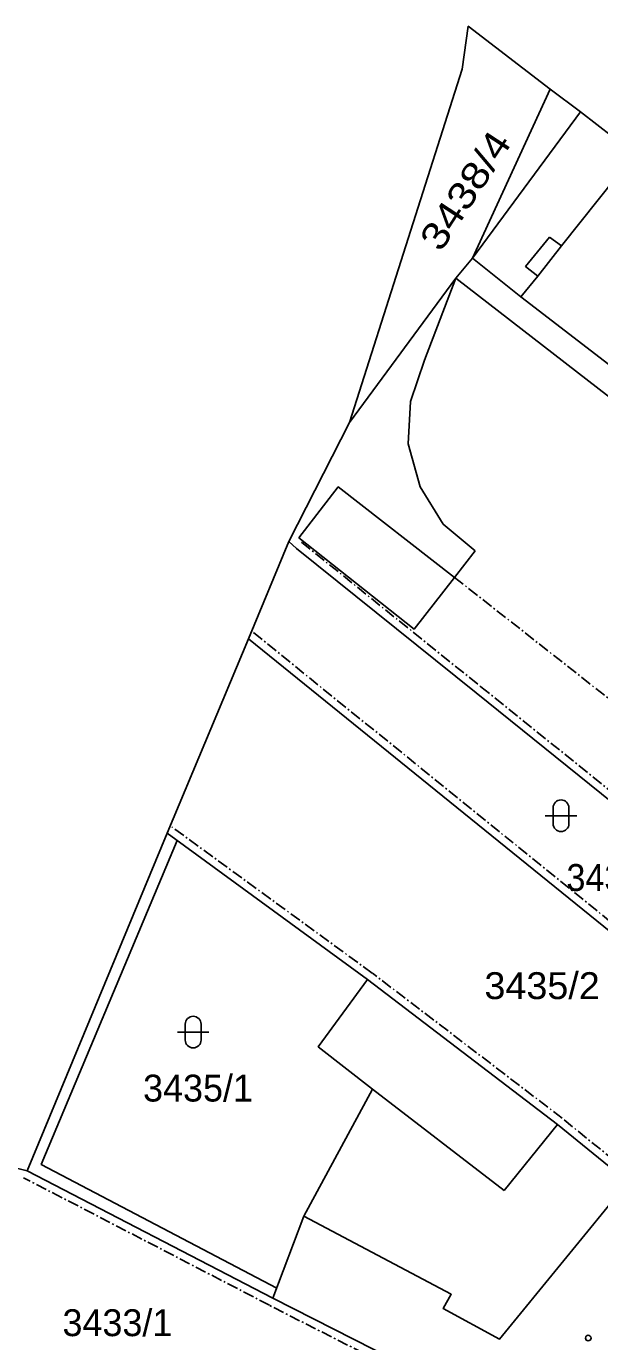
# Model space of a CAD drawing. Extents: x -568530 to -568223, y -1154101 to -1153740.
# Drawn here: x -568440.5 to -568404.2, y -1153886.3 to -1153803.1 of the extents above; entities that cross this region are included whole.
import ezdxf

# ---------------------------------------------------------------- set-up
doc = ezdxf.new("R2010")
doc.units = 0
doc.header["$LTSCALE"] = 0.14
doc.linetypes.add('DOT_DASHED', pattern=[7.7, 5, -1.2, 0.3, -1.2])
for name, color, linetype, lineweight in [('1', 7, 'Continuous', 25), ('25', 7, 'Continuous', 13), ('4', 7, 'Continuous', 25), ('6', 7, 'DOT_DASHED', 25)]:
    doc.layers.add(name, color=color, linetype=linetype, lineweight=lineweight)
doc.layers.add('18', color=7, linetype='Continuous')

msp = doc.modelspace()

# ---------------------------------------------------------------- linework, layer by layer
at = {"layer": '1'}
for p, q in [((-568407.31, -1153807.12), (-568405.4, -1153808.54)), ((-568412.24, -1153817.81), (-568405.4, -1153808.54)), ((-568405.4, -1153808.54), (-568401.97, -1153811.21)), ((-568420.02, -1153828.2), (-568413.29, -1153819.07)), ((-568423.86, -1153835.73), (-568420.02, -1153828.2))]:
    msp.add_line(p, q, dxfattribs=at)
for points in [[(-568420.02, -1153828.2), (-568412.89, -1153805.86), (-568412.5, -1153803.14), (-568407.31, -1153807.12)], [(-568407.36, -1153816.47), (-568406.61, -1153817.02), (-568401.97, -1153811.21), (-568388.26, -1153822.12)], [(-568408.11, -1153818.94), (-568408.87, -1153818.33), (-568407.36, -1153816.47)], [(-568413.29, -1153819.07), (-568412.24, -1153817.81), (-568409.17, -1153820.25)], [(-568408.11, -1153818.94), (-568409.17, -1153820.25), (-568393.38, -1153832.39)], [(-568426.4, -1153841.88), (-568423.86, -1153835.73), (-568423.37, -1153836.16), (-568412.01, -1153845.3), (-568383.87, -1153867.96), (-568388.09, -1153872.89)], [(-568431.55, -1153854.18), (-568426.4, -1153841.88), (-568388.09, -1153872.89), (-568395.23, -1153882.04)], [(-568395.23, -1153882.04), (-568406.86, -1153872.6), (-568418.87, -1153863.43), (-568431.55, -1153854.18), (-568440.41, -1153875.53)], [(-568418.87, -1153863.43), (-568422, -1153867.68), (-568418.57, -1153870.36), (-568422.9, -1153878.41), (-568424.86, -1153883.59)], [(-568404.79, -1153893.8), (-568410.79, -1153890.73), (-568424.86, -1153883.59), (-568440.41, -1153875.53), (-568467.48, -1153868.69)]]:
    msp.add_lwpolyline(points, dxfattribs=at)
at = {"layer": '25', "lineweight": 25}
for p, q in [((-568407.13, -1153853.57), (-568407.13, -1153852.57)), ((-568406.13, -1153852.57), (-568406.13, -1153853.57)), ((-568407.63, -1153853.07), (-568405.63, -1153853.07)), ((-568430.91, -1153866.76), (-568428.91, -1153866.76)), ((-568430.41, -1153867.26), (-568430.41, -1153866.26)), ((-568429.41, -1153866.26), (-568429.41, -1153867.26))]:
    msp.add_line(p, q, dxfattribs=at)
msp.add_circle((-568404.91, -1153886.11), 0.175, dxfattribs=at)
for centre, start, end in [((-568406.63, -1153852.57), 0.101, 180.00143), ((-568406.63, -1153853.57), 180.10243, 0.00286), ((-568429.91, -1153866.26), 0.101, 180.00143), ((-568429.91, -1153867.26), 180.10243, 0.00286)]:
    msp.add_arc(centre, 0.5, start, end, dxfattribs=at)
at = {"layer": '4'}
for p, q in [((-568412.24, -1153817.81), (-568407.31, -1153807.12)), ((-568406.61, -1153817.02), (-568408.11, -1153818.94)), ((-568412.06, -1153836.31), (-568413.37, -1153838)), ((-568410.22, -1153876.77), (-568418.57, -1153870.36)), ((-568410.22, -1153876.77), (-568406.86, -1153872.6))]:
    msp.add_line(p, q, dxfattribs=at)
for points in [[(-568413.29, -1153819.07), (-568415.28, -1153824.26), (-568416.15, -1153826.88), (-568416.31, -1153829.55), (-568415.55, -1153832.27), (-568414.08, -1153834.62), (-568412.06, -1153836.31)], [(-568369.44, -1153852.85), (-568378.94, -1153845.64), (-568379.34, -1153845.34), (-568413.29, -1153819.07)], [(-568430.93, -1153854.63), (-568439.52, -1153875.13), (-568424.62, -1153882.96)], [(-568422.9, -1153878.41), (-568413.58, -1153883.34), (-568414.1, -1153884.23), (-568410.52, -1153886.17), (-568402.39, -1153876.23)]]:
    msp.add_lwpolyline(points, dxfattribs=at)
msp.add_lwpolyline([(-568423.23, -1153835.49), (-568415.93, -1153841.27), (-568413.37, -1153838), (-568420.73, -1153832.27)], close=True, dxfattribs=at)
at = {"layer": '6'}
for p, q in [((-568423.06, -1153835.77), (-568411.7, -1153844.91)), ((-568413.37, -1153838), (-568381.04, -1153863.38)), ((-568426.09, -1153841.49), (-568388.15, -1153872.2)), ((-568411.7, -1153844.91), (-568383.96, -1153867.25)), ((-568418.58, -1153863.03), (-568431.26, -1153853.78)), ((-568406.56, -1153872.2), (-568418.57, -1153863.03)), ((-568395.31, -1153881.33), (-568406.55, -1153872.21)), ((-568425.09, -1153884.03), (-568440.64, -1153875.97)), ((-568411.02, -1153891.18), (-568425.09, -1153884.04))]:
    msp.add_line(p, q, dxfattribs=at)

# ---------------------------------------------------------------- texts
at = {"layer": '18', "width": 1.2}
msp.add_text('3438/4', height=1.7, rotation=56.9, dxfattribs=at).set_placement((-568414.248, -1153817.484))
at = {"layer": '18'}
for s, width, p in [('3436/1', 0.95, (-568406.29, -1153857.83)), ('3435/2', 1.05, (-568411.48, -1153864.67))]:
    msp.add_text(s, height=1.7, dxfattribs=dict(at, width=width)).set_placement(p)
for s, p in [('3435/1', (-568433.08, -1153871.15)), ('3433/1', (-568438.18, -1153885.99))]:
    msp.add_text(s, height=1.7, dxfattribs=at).set_placement(p)

doc.saveas('drawing.dxf')
